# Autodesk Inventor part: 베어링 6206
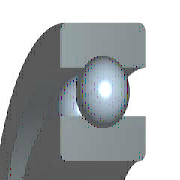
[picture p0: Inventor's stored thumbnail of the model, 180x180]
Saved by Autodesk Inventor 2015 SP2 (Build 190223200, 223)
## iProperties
Created: 2009-02
Part Number: 베어링 6206
Material: Steel, Mild
Description: 깊은 그루브 볼 베어링
Document SubType Name: Modeling
Standard: KS B 2023
Designer: KYOUNG IL JANG
Standards Organization: KS
Language: ko-KR
Size Designation: 6206 - 30 x 62 x 16
Categories: <MemberInstance><Categories><Category DisplayName="샤프트 부품" InternalName="7f7aeb1f-a693-4053-b835-cee3144e0d98" Mnemonic="SHFT"><Category DisplayName="베어링" Inter
Density: 1 g/cm^3
Appearance: Metal-Steel
Company: 한국ATC센터
IsCustomPart: 0
Author: KYOUNG IL JANG
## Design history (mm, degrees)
sketch "스케치" dims "d0" = 8.32 (= -0.26 x WD + 0.26 x BD)
  geometry: L1 (3.84, 23)-(12.16, 23); L2 (8, 23)-(8, 18.84); L3 (8, 23)-(8, 27.16); L4 (4.909, 20.216)-(0, 20.216); L5 (0, 15)-(16, 15); L6 (4.909, 25.784)-(0, 25.784); L7 (0, 31)-(16, 31); L8 (16, 15)-(16, 20.216); L9 (11.091, 20.216)-(16, 20.216); L10 (11.091, 25.784)-(16, 25.784); L11 (16, 31)-(16, 25.784); L12 (-1.4, 0)-(8.4, 0) reference; L13 (0, -0.3)-(0, 5.3) reference
  constraints: 22 end point, 4 point on line, 2 collinear, 2 perpendicular, 2 symmetric about line, 1 midpoint, 1 parallel, 14 other
  dimensions: "d9" = 30 diameter of L5 L12 (= WD); "d11" = 62 diameter of L7 L12 (= BD); "d12" = 16 distance between parallel lines of L8 L13 (= KB); "d13" = 40.432 diameter of L9 L12 (= 0.326 x BD + 0.674 x WD)
revolve "본체" stored, may be unused: angle "d6" = 90 deg
revolve "볼" stored, may be unused: angle "d7" = 90 deg
pattern_circular "IDS_ARRAYBALL[SIMPL:T]" dims angle "d3" = 360 deg
body "Solid1"
fillet "모깎기1" dims "d1" = 1 (= KRS)
other parameters: "WD" = 30 [user parameter; used in 5 equation terms], "BD" = 62 [user parameter; used in 5 equation terms], "KB" = 16 [user parameter; used in 1 equation term], "KRS" = 1 [user parameter; used in 1 equation term], "d4" = 0, "d5" = 0, "d8" = 0, "d14" = 0, "d15" = 0, "BBA" = 0 [user parameter], "BC0" = 1.12e+07 [user parameter], "BC" = 1.95e+07 [user parameter], "BR" = 31 (= 0.5 x BD) [user parameter], "WR" = 15 (= 0.5 x WD) [user parameter]
